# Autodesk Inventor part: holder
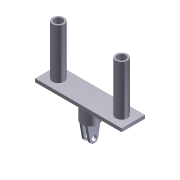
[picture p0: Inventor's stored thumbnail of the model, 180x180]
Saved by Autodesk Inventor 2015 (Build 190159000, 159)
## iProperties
Created: 2020-09
Part Number: holder
Material: 一般
Document SubType Name: Modeling
Designer: 徐冠倫
Mass: 3548.88 g
Surface Area: 4611.53 cm^2
Volume: 3548.88 cm^3
Density: 1 g/cm^3
Appearance: 預設
Author: 徐冠倫
Author: IANNIAN
Title: D:\Desktop\OCW-Computer-Aided Engineering Drawing\OCW_Topic 06：組合圖與機構模擬(進階)\6-1_Flexibility\Mechanical Gripper(piston)\Mechanical Gripper(STP)\holder.stp
Creation Date: 2020-09-04
Sending System: Autodesk Inventor 2020
Preprocessor: ST-DEVELOPER v18
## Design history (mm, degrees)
node "holder1"
body "Solid1"
node "Base1"
